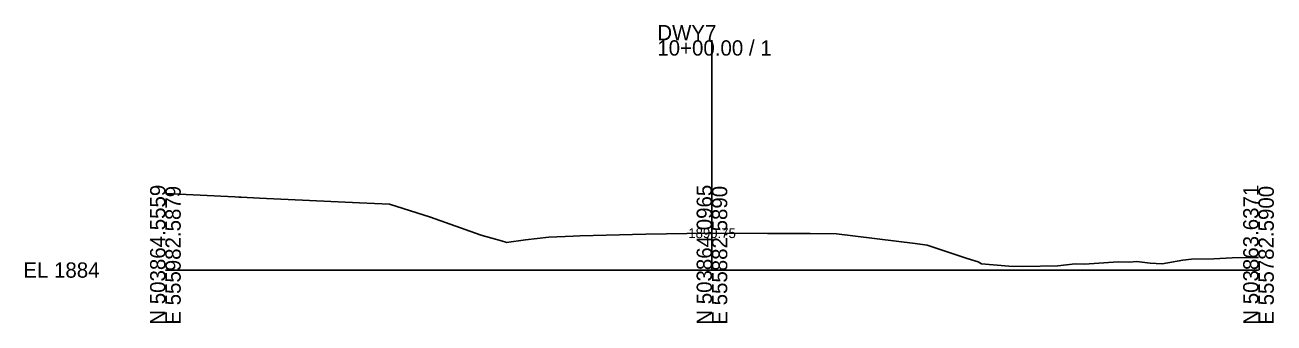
# Model space of a CAD drawing. Extents: x -26 to 1503, y -10 to 1052.
# Drawn here: x -25.7 to 202.8, y -9.7 to 44.8 of the extents above; entities that cross this region are included whole.
import ezdxf

# ---------------------------------------------------------------- set-up
doc = ezdxf.new("R2010")
doc.units = 0
for name, color, linetype in [('Default', 7, 'Continuous'), ('Exist Cross Section Cell', 7, 'Continuous'), ('Exist XS Center Line Elevation Label', 7, 'Continuous'), ('Exist XS Ground Line', 7, 'Continuous')]:
    doc.layers.add(name, color=color, linetype=linetype)

msp = doc.modelspace()

# ---------------------------------------------------------------- linework, layer by layer
at = {"layer": 'Exist Cross Section Cell'}
for p, q in [((100, 0), (100, 42.04)), ((0, 0), (100, 0)), ((100, 0), (200, 0))]:
    msp.add_line(p, q, dxfattribs=at)
at = {"layer": 'Exist XS Ground Line'}
for p, q in [((0, 14.01), (12.73, 13.37)), ((12.73, 13.37), (13.42, 13.33)), ((13.42, 13.33), (13.88, 13.32)), ((13.88, 13.32), (17.22, 13.16)), ((17.22, 13.16), (35.51, 12.29)), ((35.51, 12.29), (41.03, 12.04)), ((41.03, 12.04), (48.5, 9.67)), ((48.5, 9.67), (57.61, 6.43)), ((57.61, 6.43), (57.95, 6.31)), ((57.95, 6.31), (60.38, 5.63)), ((60.38, 5.63), (62.1, 5.16)), ((62.1, 5.16), (62.41, 5.04)), ((62.41, 5.04), (65.91, 5.54)), ((65.91, 5.54), (70.17, 6.04)), ((70.17, 6.04), (74.61, 6.2)), ((74.61, 6.2), (75.84, 6.29)), ((75.84, 6.29), (87.88, 6.57)), ((87.88, 6.57), (99.19, 6.75)), ((99.19, 6.75), (100, 6.75)), ((100, 6.75), (110.17, 6.71)), ((110.17, 6.71), (115.9, 6.67)), ((115.9, 6.67), (117.99, 6.66)), ((117.99, 6.66), (122.79, 6.64)), ((122.79, 6.64), (137.21, 4.86)), ((137.21, 4.86), (139.39, 4.56)), ((139.39, 4.56), (144.15, 2.99)), ((144.15, 2.99), (146.72, 2.12)), ((199, 2.27), (200, 2.3)), ((146.72, 2.12), (148.73, 1.49)), ((148.73, 1.49), (149.31, 1.11)), ((149.31, 1.11), (154.29, 0.74)), ((154.29, 0.74), (156.87, 0.63)), ((156.87, 0.63), (163.29, 0.75)), ((163.29, 0.75), (166.46, 1.11)), ((166.46, 1.11), (168.18, 1.1)), ((168.18, 1.1), (174.34, 1.52)), ((174.34, 1.52), (176.36, 1.47)), ((176.36, 1.47), (177.71, 1.58)), ((177.71, 1.58), (180.18, 1.24)), ((180.18, 1.24), (182.4, 1.15)), ((182.4, 1.15), (186.14, 1.78)), ((186.14, 1.78), (187.76, 1.98)), ((187.76, 1.98), (191.83, 2.05)), ((191.83, 2.05), (195.21, 2.21)), ((195.21, 2.21), (199, 2.27))]:
    msp.add_line(p, q, dxfattribs=at)

# ---------------------------------------------------------------- texts
at = {"layer": 'Default'}
msp.add_text('-', height=0.0001, dxfattribs=at).set_placement((0, 0))
at = {"layer": 'Exist Cross Section Cell'}
for s, p in [('DWY7', (90, 42.04)), ('10+00.00 / 1', (90, 39.24)), ('EL 1884', (-26, -1.4))]:
    msp.add_text(s, height=2.8, dxfattribs=at).set_placement(p)
for s, p in [('N 503864.5559', (0, -10)), ('E 555982.5879', (2.8, -10)), ('N 503864.0965', (100, -10)), ('E 555882.5890', (102.8, -10)), ('N 503863.6371', (200, -10)), ('E 555782.5900', (202.8, -10))]:
    msp.add_text(s, height=2.8, rotation=90, dxfattribs=at).set_placement(p)
at = {"layer": 'Exist XS Center Line Elevation Label'}
msp.add_text('1890.75', height=1.8, dxfattribs=at).set_placement((95.67, 5.85))

doc.saveas('drawing.dxf')
